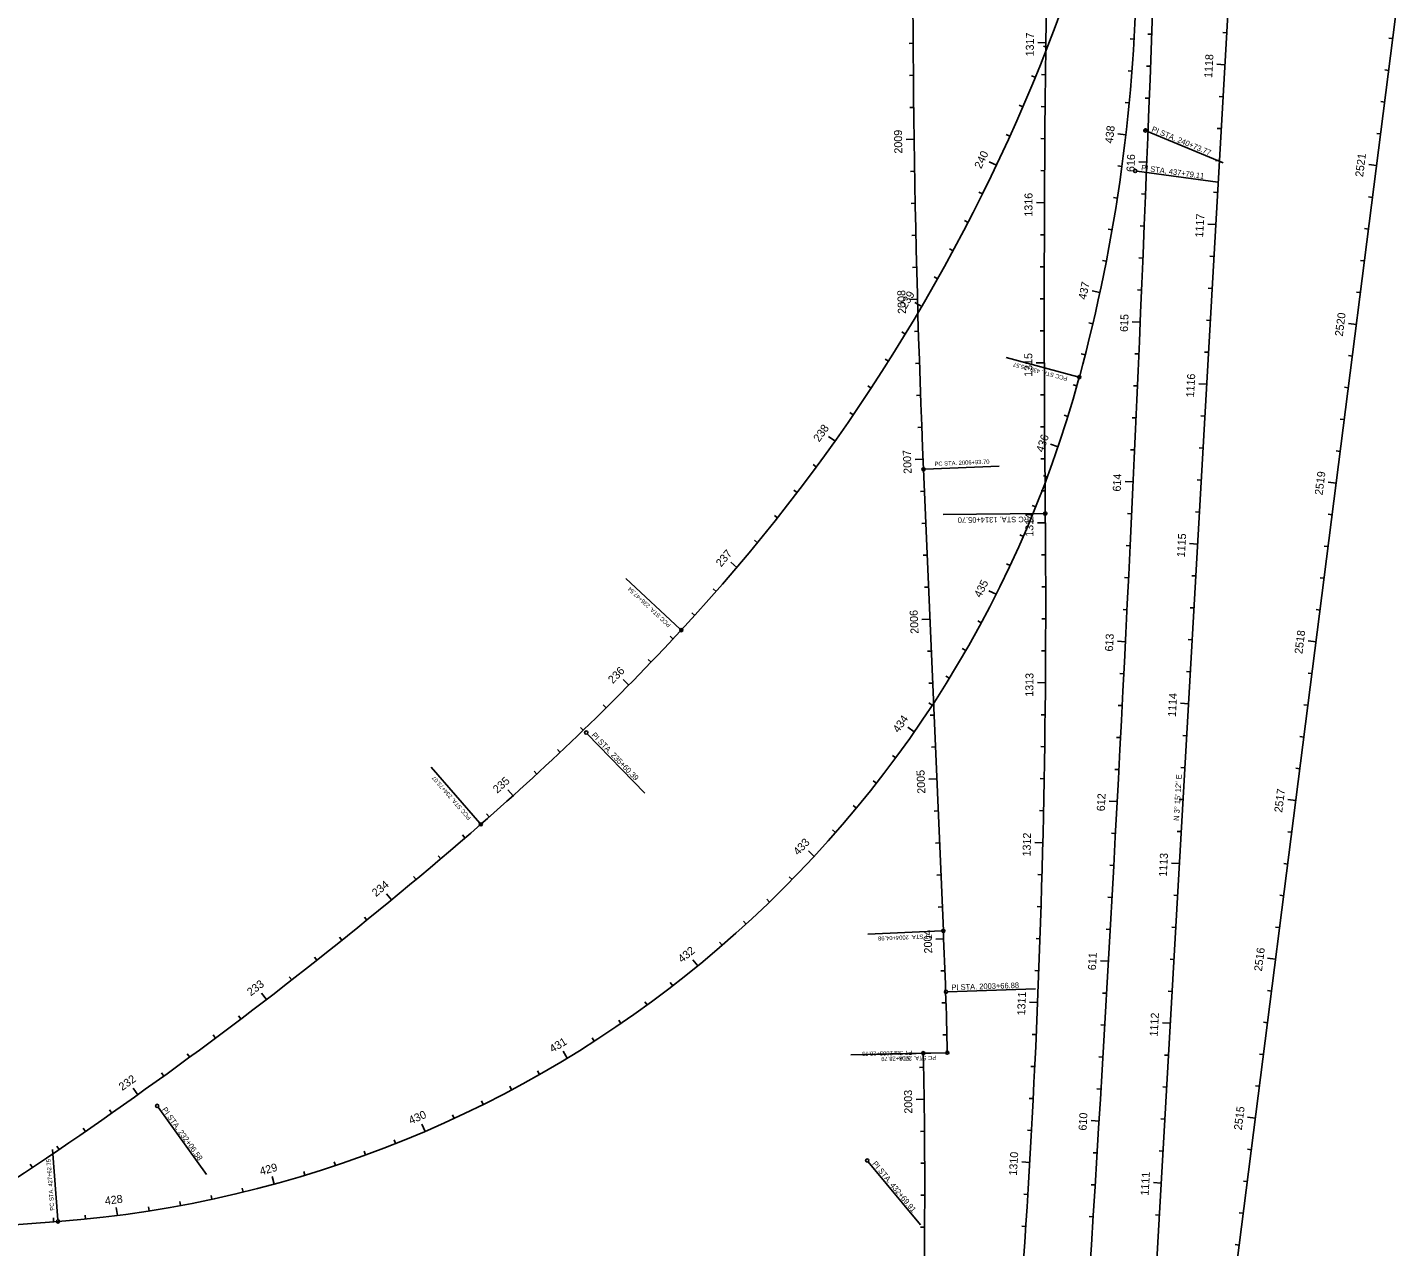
# Model space of a CAD drawing. Extents: x 919452 to 931278, y 583254 to 665650.
# Drawn here: x 928386 to 929242, y 636768 to 637530 of the extents above; entities that cross this region are included whole.
import ezdxf

# ---------------------------------------------------------------- set-up
doc = ezdxf.new("R2010")
doc.units = 0
for name, color, linetype in [('CLConst_dp', 7, 'Continuous'), ('CurveDataLabel_dp', 7, 'Continuous'), ('StationTicL_dp', 7, 'Continuous'), ('StationTicS_dp', 7, 'Continuous'), ('TextBLStation', 7, 'Continuous'), ('TextLabel', 7, 'Continuous')]:
    doc.layers.add(name, color=color, linetype=linetype)

msp = doc.modelspace()

# ---------------------------------------------------------------- linework, layer by layer
at = {"layer": 'CLConst_dp'}
for p, q in [((929063.91, 636273.75), (929152.38, 637830.35)), ((929141.47, 636757.31), (929241.91, 637546.46)), ((928958.02, 636965.18), (928945.65, 637253.64)), ((928945.5, 636888.7), (928960.5, 636889.03)), ((928197.18, 636767.96), (928404.75, 636783.58))]:
    msp.add_line(p, q, dxfattribs=at)
for centre, radius, start, end in [((900459.43, 638571.38), 28647.89, 355.955427, 0.622371), ((942221.08, 637355.55), 13200, 175.794488, 180.562502), ((936146.52, 637562.53), 7207.49, 175.47906, 182.456288), ((927949.43, 637937.64), 1152.92, 317.11857, 357.69675), ((928044.2, 637581.6), 1034.77, 344.85215, 359.56031), ((928350.92, 637498.56), 717, 274.3056, 344.85215), ((923022, 637167.05), 6000, 353.771004, 0.562502), ((927591.11, 638270.4), 1641.92, 311.0304, 317.11857), ((926819.39, 639157.21), 2817.49, 300.15904, 311.0304), ((925288.17, 636807.76), 3673.23, 1.26779, 2.45629), ((925288.17, 636807.76), 3658.23, 353.771, 1.26779)]:
    msp.add_arc(centre, radius, start, end, dxfattribs=at)
at = {"layer": 'CurveDataLabel_dp'}
for p, q in [((929085.21, 637465.04), (929132.92, 637445.19)), ((929078.9, 637439.97), (929129.62, 637433.03)), ((929042.04, 637311.46), (928997.3, 637323.57)), ((928946.65, 637253.68), (928992.91, 637255.67)), ((929020.71, 637225.95), (928957.88, 637225.33)), ((928793.51, 637153.78), (928759.54, 637185.33)), ((928735.53, 637088.4), (928771.53, 637051.21)), ((928668.31, 637032.55), (928637.88, 637067.52)), ((928957.02, 636965.14), (928910.78, 636963.16)), ((928960.65, 636927.15), (929015.58, 636928.94)), ((928944.5, 636888.68), (928900.21, 636887.7)), ((928959.5, 636889.01), (928913.2, 636887.98)), ((928944.5, 636888.68), (928925.34, 636888.25)), ((928467.3, 636854.99), (928497.46, 636812.86)), ((928404.68, 636784.58), (928401.37, 636828.45)), ((928911.12, 636820.89), (928943.74, 636781.43))]:
    msp.add_line(p, q, dxfattribs=at)
for centre in [(929084.29, 637465.42), (929077.91, 637440.11), (929043.01, 637311.2), (928945.65, 637253.64), (929021.71, 637225.96), (928794.25, 637153.1), (928734.83, 637089.12), (928668.96, 637031.8), (928958.02, 636965.18), (928959.65, 636927.12), (928945.5, 636888.7), (928945.5, 636888.7), (928960.5, 636889.03), (928466.72, 636855.8), (928910.48, 636821.66), (928404.75, 636783.58)]:
    msp.add_circle(centre, 1, dxfattribs=at)
at = {"layer": 'StationTicL_dp'}
for p, q in [((929022.1, 637520.25), (929017.1, 637520.31)), ((929133.97, 637506.45), (929128.98, 637506.74)), ((928939.76, 637459.85), (928934.76, 637459.78)), ((929072.11, 637462.72), (929067.14, 637463.3)), ((928991.2, 637443.74), (928986.68, 637445.88)), ((929085.19, 637445.59), (929080.19, 637445.78)), ((929228.8, 637443.42), (929223.84, 637444.05)), ((929021.24, 637420.26), (929016.24, 637420.28)), ((929128.3, 637406.62), (929123.31, 637406.9)), ((929055.84, 637364.09), (929050.96, 637365.15)), ((928941.88, 637359.87), (928936.88, 637359.73)), ((928944.5, 637355.35), (928940.18, 637357.87)), ((929081.08, 637345.67), (929076.09, 637345.88)), ((929216.17, 637344.22), (929211.21, 637344.85)), ((929021.12, 637320.26), (929016.12, 637320.24)), ((929122.62, 637306.78), (929117.63, 637307.06)), ((928890.31, 637271.34), (928886.23, 637274.23)), ((929029.71, 637267.63), (929024.98, 637269.24)), ((928945.38, 637259.93), (928940.39, 637259.72)), ((929076.63, 637245.77), (929071.64, 637246)), ((929203.55, 637245.02), (929198.59, 637245.65)), ((929021.77, 637220.26), (929016.77, 637220.21)), ((929116.95, 637206.94), (929111.96, 637207.22)), ((928829.06, 637192.34), (928825.24, 637195.57)), ((928991.02, 637175.5), (928986.55, 637177.76)), ((928949.66, 637160.02), (928944.67, 637159.81)), ((929071.83, 637145.89), (929066.83, 637146.13)), ((929190.92, 637145.82), (929185.96, 637146.45)), ((928761.4, 637118.73), (928757.83, 637122.24)), ((929021.82, 637120.26), (929016.82, 637120.3)), ((929111.27, 637107.1), (929106.28, 637107.38)), ((928939.89, 637089.66), (928935.78, 637092.51)), ((928953.95, 637060.12), (928948.95, 637059.9)), ((928689.13, 637049.64), (928685.78, 637053.36)), ((929066.68, 637046.02), (929061.69, 637046.28)), ((929178.29, 637046.62), (929173.33, 637047.25)), ((929020.21, 637020.27), (929015.21, 637020.4)), ((928877.33, 637011.75), (928873.66, 637015.14)), ((929105.6, 637007.26), (929100.61, 637007.54)), ((928613.22, 636984.55), (928610.04, 636988.4)), ((928958.23, 636960.21), (928953.24, 636960)), ((928804.54, 636943.3), (928801.38, 636947.17)), ((929061.18, 636946.17), (929056.19, 636946.45)), ((929165.67, 636947.42), (929160.71, 636948.06)), ((928535, 636922.26), (928531.95, 636926.23)), ((929016.93, 636920.33), (929011.93, 636920.53)), ((929099.92, 636907.42), (929094.93, 636907.71)), ((928722.94, 636885.63), (928720.35, 636889.9)), ((928454.61, 636862.79), (928451.71, 636866.86)), ((928946.02, 636859.92), (928941.03, 636859.85)), ((928634.12, 636839.86), (928632.15, 636844.45)), ((929055.33, 636846.34), (929050.34, 636846.64)), ((929153.04, 636848.22), (929148.08, 636848.86)), ((929011.98, 636820.45), (929006.99, 636820.74)), ((928539.8, 636806.89), (928538.48, 636811.71)), ((929094.25, 636807.58), (929089.26, 636807.87)), ((928441.81, 636787.35), (928441.18, 636792.3))]:
    msp.add_line(p, q, dxfattribs=at)
at = {"layer": 'StationTicS_dp'}
for p, q in [((929088.22, 637525.53), (929085.72, 637525.62)), ((929135.11, 637526.42), (929132.61, 637526.56)), ((928939.15, 637519.84), (928936.65, 637519.83)), ((929022.94, 637517.16), (929020.61, 637518.07)), ((929077.27, 637522.49), (929074.78, 637522.63)), ((929238.9, 637522.78), (929236.42, 637523.1)), ((929021.87, 637500.25), (929019.37, 637500.28)), ((929075.94, 637502.54), (929073.44, 637502.73)), ((929087.48, 637505.54), (929084.98, 637505.64)), ((929236.37, 637502.94), (929233.89, 637503.26)), ((928939.3, 637499.84), (928936.8, 637499.82)), ((929015.48, 637498.6), (929013.17, 637499.55)), ((929074.22, 637482.61), (929071.73, 637482.85)), ((929086.73, 637485.56), (929084.23, 637485.65)), ((929132.84, 637486.49), (929130.34, 637486.63)), ((929233.85, 637483.1), (929231.37, 637483.42)), ((928939.5, 637479.84), (928937, 637479.82)), ((929007.71, 637480.17), (929005.41, 637481.16)), ((929021.67, 637480.25), (929019.17, 637480.28)), ((929085.97, 637465.57), (929083.47, 637465.67)), ((929131.7, 637466.52), (929129.21, 637466.66)), ((928999.61, 637461.88), (928997.33, 637462.92)), ((929021.49, 637460.25), (929018.99, 637460.27)), ((929231.32, 637463.26), (929228.84, 637463.58)), ((929021.35, 637440.26), (929018.85, 637440.27)), ((929069.62, 637442.88), (929067.14, 637443.21)), ((929130.57, 637446.55), (929128.07, 637446.69)), ((928940.07, 637439.85), (928937.57, 637439.81)), ((928982.48, 637425.74), (928980.24, 637426.85)), ((929066.75, 637423.09), (929064.28, 637423.47)), ((929084.39, 637425.6), (929081.9, 637425.7)), ((929129.43, 637426.58), (929126.94, 637426.73)), ((929226.27, 637423.58), (929223.79, 637423.9)), ((928940.44, 637419.85), (928937.94, 637419.8)), ((928973.44, 637407.9), (928971.22, 637409.05)), ((929083.59, 637405.62), (929081.09, 637405.72)), ((928940.86, 637399.86), (928938.36, 637399.8)), ((929021.15, 637400.26), (929018.65, 637400.26)), ((929063.49, 637403.35), (929061.03, 637403.78)), ((929223.75, 637403.74), (929221.27, 637404.06)), ((928964.1, 637390.22), (928961.9, 637391.4)), ((929021.1, 637380.26), (929018.6, 637380.26)), ((929059.86, 637383.69), (929057.41, 637384.16)), ((929082.77, 637385.64), (929080.27, 637385.74)), ((929127.16, 637386.65), (929124.67, 637386.79)), ((929221.22, 637383.9), (929218.74, 637384.22)), ((928941.34, 637379.86), (928938.84, 637379.8)), ((928954.45, 637372.7), (928952.27, 637373.92)), ((929081.93, 637365.65), (929079.43, 637365.76)), ((929126.03, 637366.68), (929123.53, 637366.82)), ((929218.7, 637364.06), (929216.22, 637364.38)), ((929021.08, 637360.26), (929018.58, 637360.26)), ((929124.89, 637346.71), (929122.4, 637346.85)), ((928934.25, 637338.18), (928932.11, 637339.48)), ((928942.47, 637339.88), (928939.97, 637339.8)), ((929021.09, 637340.26), (929018.59, 637340.25)), ((929051.45, 637344.58), (929049.02, 637345.16)), ((928923.7, 637321.18), (928921.59, 637322.52)), ((929046.68, 637325.16), (929044.26, 637325.78)), ((929080.22, 637325.69), (929077.72, 637325.8)), ((929123.76, 637326.74), (929121.26, 637326.89)), ((929213.65, 637324.38), (929211.17, 637324.7)), ((928943.11, 637319.89), (928940.61, 637319.8)), ((928912.86, 637304.38), (928910.77, 637305.75)), ((929041.53, 637305.83), (929039.13, 637306.51)), ((929079.34, 637305.71), (929076.85, 637305.82)), ((929211.12, 637304.54), (929208.64, 637304.86)), ((928943.81, 637299.9), (928941.31, 637299.81)), ((929021.19, 637300.26), (929018.69, 637300.25)), ((928901.73, 637287.76), (928899.67, 637289.17)), ((929035.89, 637286.65), (929033.5, 637287.39)), ((929078.45, 637285.73), (929075.96, 637285.84)), ((929121.49, 637286.81), (929118.99, 637286.95)), ((928944.57, 637279.92), (928942.07, 637279.82)), ((929021.29, 637280.26), (929018.79, 637280.24)), ((929208.6, 637284.7), (929206.12, 637285.02)), ((929021.42, 637260.26), (929018.92, 637260.24)), ((929077.55, 637265.75), (929075.05, 637265.86)), ((929120.35, 637266.84), (929117.86, 637266.98)), ((929206.07, 637264.86), (929203.59, 637265.18)), ((928878.62, 637255.12), (928876.6, 637256.6)), ((929023.01, 637248.78), (929020.66, 637249.66)), ((929119.22, 637246.87), (929116.72, 637247.02)), ((928866.64, 637239.1), (928864.65, 637240.62)), ((928946.24, 637239.95), (928943.74, 637239.84)), ((929021.58, 637240.26), (929019.08, 637240.24)), ((929015.78, 637230.14), (929013.46, 637231.07)), ((929075.7, 637225.79), (929073.2, 637225.91)), ((929118.08, 637226.91), (929115.59, 637227.05)), ((928854.38, 637223.3), (928852.42, 637224.85)), ((928947.09, 637219.97), (928944.59, 637219.86)), ((929201.02, 637225.18), (929198.54, 637225.5)), ((928841.85, 637207.71), (928839.92, 637209.29)), ((929008.04, 637211.7), (929005.74, 637212.7)), ((929021.91, 637200.26), (929019.41, 637200.24)), ((929074.75, 637205.81), (929072.25, 637205.93)), ((929198.5, 637205.34), (929196.02, 637205.66)), ((928947.95, 637199.99), (928945.45, 637199.88)), ((928999.78, 637193.48), (928997.52, 637194.55)), ((929073.79, 637185.84), (929071.29, 637185.96)), ((929115.81, 637186.97), (929113.32, 637187.11)), ((929195.97, 637185.5), (929193.49, 637185.82)), ((928816, 637177.19), (928814.12, 637178.84)), ((928948.81, 637180.01), (928946.31, 637179.9)), ((929021.99, 637180.26), (929019.49, 637180.25)), ((929072.82, 637165.86), (929070.32, 637165.98)), ((929114.68, 637167), (929112.18, 637167.14)), ((929193.45, 637165.66), (929190.97, 637165.98)), ((928802.68, 637162.27), (928800.83, 637163.95)), ((928981.76, 637157.78), (928979.56, 637158.97)), ((929022, 637160.26), (929019.5, 637160.26)), ((928789.1, 637147.58), (928787.28, 637149.29)), ((928972.01, 637140.32), (928969.84, 637141.57)), ((929021.94, 637140.26), (929019.44, 637140.27)), ((929113.54, 637147.03), (929111.05, 637147.18)), ((928775.34, 637133.07), (928773.53, 637134.81)), ((928950.52, 637140.04), (928948.02, 637139.93)), ((928961.78, 637123.13), (928959.65, 637124.44)), ((929070.83, 637125.91), (929068.33, 637126.04)), ((929112.41, 637127.07), (929109.91, 637127.21)), ((929188.4, 637125.98), (929185.92, 637126.3)), ((928951.38, 637120.06), (928948.88, 637119.95)), ((928747.28, 637104.56), (928745.52, 637106.34)), ((928951.07, 637106.24), (928948.97, 637107.61)), ((929069.81, 637105.94), (929067.31, 637106.06)), ((929185.87, 637106.14), (929183.39, 637106.46)), ((928952.24, 637100.08), (928949.74, 637099.97)), ((929021.63, 637100.26), (929019.13, 637100.29)), ((928733, 637090.57), (928731.26, 637092.36)), ((929068.78, 637085.96), (929066.28, 637086.09)), ((929110.14, 637087.13), (929107.64, 637087.27)), ((929183.34, 637086.3), (929180.86, 637086.62)), ((928718.54, 637076.75), (928716.82, 637078.56)), ((928928.26, 637073.39), (928926.24, 637074.87)), ((928953.09, 637080.1), (928950.59, 637079.99)), ((929021.37, 637080.26), (929018.87, 637080.3)), ((928703.92, 637063.1), (928702.22, 637064.94)), ((929067.74, 637065.99), (929065.24, 637066.12)), ((929109, 637067.16), (929106.51, 637067.31)), ((929180.82, 637066.46), (929178.34, 637066.78)), ((928916.18, 637057.45), (928914.2, 637058.99)), ((929021.05, 637060.26), (929018.55, 637060.31)), ((929107.87, 637047.2), (929105.37, 637047.34)), ((928674.18, 637036.35), (928672.53, 637038.23)), ((928903.65, 637041.86), (928901.73, 637043.45)), ((928954.81, 637040.13), (928952.31, 637040.03)), ((929020.66, 637040.27), (929018.16, 637040.32)), ((928659.08, 637023.24), (928657.45, 637025.13)), ((928890.7, 637026.62), (928888.82, 637028.27)), ((929065.61, 637026.05), (929063.11, 637026.18)), ((929106.73, 637027.23), (929104.24, 637027.37)), ((929175.77, 637026.78), (929173.29, 637027.1)), ((928643.89, 637010.23), (928642.27, 637012.14)), ((928955.66, 637020.15), (928953.17, 637020.05)), ((929064.52, 637006.08), (929062.02, 637006.21)), ((929173.24, 637006.94), (929170.76, 637007.26)), ((928628.6, 636997.33), (928626.99, 636999.25)), ((928863.55, 636997.26), (928861.76, 636999)), ((928956.52, 637000.17), (928954.02, 637000.06)), ((929019.68, 637000.28), (929017.18, 637000.35)), ((929063.42, 636986.11), (929060.92, 636986.24)), ((929104.46, 636987.29), (929101.97, 636987.43)), ((929170.72, 636987.1), (929168.24, 636987.42)), ((928849.36, 636983.15), (928847.63, 636984.95)), ((928957.38, 636980.19), (928954.88, 636980.08)), ((929019.09, 636980.29), (929016.6, 636980.37)), ((928597.75, 636971.87), (928596.18, 636973.81)), ((928834.8, 636969.45), (928833.11, 636971.3)), ((928582.2, 636959.3), (928580.63, 636961.25)), ((929062.31, 636966.14), (929059.81, 636966.28)), ((929103.33, 636967.32), (929100.83, 636967.47)), ((929168.19, 636967.26), (929165.71, 636967.58)), ((928819.85, 636956.16), (928818.22, 636958.06)), ((929018.44, 636960.3), (929015.94, 636960.39)), ((928566.55, 636946.84), (928565, 636948.8)), ((929102.19, 636947.36), (929099.7, 636947.5)), ((928550.82, 636934.49), (928549.28, 636936.47)), ((928959.01, 636940.22), (928956.51, 636940.13)), ((929017.72, 636940.31), (929015.22, 636940.41)), ((928788.88, 636930.86), (928787.35, 636932.84)), ((929060.04, 636926.2), (929057.54, 636926.35)), ((929101.06, 636927.39), (929098.56, 636927.53)), ((929163.14, 636927.58), (929160.66, 636927.9)), ((928772.87, 636918.87), (928771.4, 636920.89)), ((928959.67, 636920.23), (928957.18, 636920.16)), ((928519.09, 636910.14), (928517.58, 636912.13)), ((928756.54, 636907.32), (928755.13, 636909.39)), ((929058.88, 636906.24), (929056.39, 636906.38)), ((929160.62, 636907.74), (929158.14, 636908.06)), ((928503.09, 636898.13), (928501.6, 636900.13)), ((928739.89, 636896.24), (928738.54, 636898.34)), ((928960.23, 636900.24), (928957.73, 636900.18)), ((929016.07, 636900.35), (929013.57, 636900.46)), ((928487.02, 636886.24), (928485.54, 636888.25)), ((929057.71, 636886.27), (929055.22, 636886.42)), ((929098.79, 636887.45), (929096.29, 636887.6)), ((929158.09, 636887.9), (929155.61, 636888.22)), ((928470.85, 636874.46), (928469.39, 636876.48)), ((928705.7, 636875.49), (928704.47, 636877.66)), ((928945.69, 636879.91), (928943.19, 636879.87)), ((929015.15, 636880.37), (929012.65, 636880.49)), ((928688.19, 636865.84), (928687.01, 636868.04)), ((929056.53, 636866.3), (929054.03, 636866.45)), ((929097.65, 636867.49), (929095.16, 636867.63)), ((929155.57, 636868.06), (929153.09, 636868.38)), ((928670.41, 636856.68), (928669.3, 636858.91)), ((929014.16, 636860.39), (929011.66, 636860.52)), ((928438.28, 636851.24), (928436.84, 636853.29)), ((928652.38, 636848.02), (928651.33, 636850.28)), ((928421.87, 636839.81), (928420.45, 636841.86)), ((929013.1, 636840.42), (929010.61, 636840.56)), ((929096.52, 636847.52), (929094.02, 636847.66)), ((928615.64, 636832.22), (928614.72, 636834.54)), ((928946.26, 636839.92), (928943.76, 636839.9)), ((928405.38, 636828.49), (928403.97, 636830.56)), ((928596.95, 636825.09), (928596.09, 636827.44)), ((929054.12, 636826.38), (929051.63, 636826.53)), ((929095.38, 636827.55), (929092.89, 636827.69)), ((929150.52, 636828.38), (929148.04, 636828.7)), ((928388.81, 636817.29), (928387.42, 636819.37)), ((928578.07, 636818.49), (928577.28, 636820.87)), ((928946.38, 636819.92), (928943.88, 636819.91)), ((928559.02, 636812.42), (928558.29, 636814.82)), ((929052.9, 636806.41), (929050.4, 636806.57)), ((929147.99, 636808.54), (929145.51, 636808.86)), ((928500.94, 636797.43), (928500.42, 636799.88)), ((928520.44, 636801.89), (928519.84, 636804.32)), ((928946.39, 636799.92), (928943.89, 636799.92)), ((929010.79, 636800.49), (929008.3, 636800.64)), ((928461.61, 636790.16), (928461.23, 636792.63)), ((928481.33, 636793.52), (928480.87, 636795.98)), ((928402.01, 636783.38), (928401.83, 636785.87)), ((928421.94, 636785.09), (928421.69, 636787.57)), ((929009.54, 636780.53), (929007.04, 636780.69)), ((929051.66, 636786.45), (929049.16, 636786.61)), ((929093.11, 636787.61), (929090.62, 636787.76)), ((929145.47, 636788.7), (929142.99, 636789.02)), ((928946.29, 636779.92), (928943.79, 636779.94)), ((929142.94, 636768.86), (929140.46, 636769.18))]:
    msp.add_line(p, q, dxfattribs=at)

# ---------------------------------------------------------------- texts
at = {"layer": 'CurveDataLabel_dp'}
for s, height, rotation, p in [('PI STA. 240+73.77', 3.5, 337.40766, (929087.86, 637464.88)), ('PI STA. 437+79.11', 3.5, 352.20623, (929081.49, 637440.5)), ('PCC STA. 436+45.57', 2.625, 164.85215, (929035.79, 637311.34)), ('PC STA. 2006+93.70', 2.625, 2.45629, (928952.57, 637255.69)), ('PRC STA. 1314+05.70', 3.5, 180.5625, (929014.73, 637224.14)), ('PCC STA. 236+47.54', 2.625, 137.11857, (928787.93, 637156.58)), ('PI STA. 235+60.39', 3.5, 314.07448, (928737.89, 637087.21)), ('PCC STA. 234+73.07', 2.625, 131.0304, (928663.05, 637035.93)), ('PT STA. 2004+04.98', 2.625, 182.45629, (928951.1, 636963.14)), ('PI STA. 2003+66.88', 3.5, 1.86204, (928963.12, 636928.11)), ('PT Sta 2003+28.79', 2.625, 181.26779, (928938.46, 636890.29)), ('PC STA. 2003+28.79', 2.625, 181.26779, (928953.54, 636887.13)), (' STA. ', 2.625, 181.26779, (928938.54, 636886.79)), ('PI STA. 232+06.58', 3.5, 305.59472, (928469.47, 636853.46)), ('PC STA. 427+62.75', 2.625, 94.3056, (928402.48, 636790.43)), ('PI STA. 432+69.91', 3.5, 309.57888, (928913.39, 636819.52))]:
    msp.add_text(s, height=height, rotation=rotation, dxfattribs=at).set_placement(p)
at = {"layer": 'TextBLStation'}
for s, rotation, p in [('1317', 89.28507, (929014.5, 637511.63)), ('1118', 86.74679, (929125.99, 637498.08)), ('438', 83.40331, (929063.91, 637457.06)), ('2009', 90.81632, (928932.38, 637450.96)), ('240', 64.63446, (928981.63, 637441.06)), ('616', 87.74782, (929077.44, 637439.35)), ('2521', 82.74679, (929220.3, 637436.06)), ('1316', 89.71913, (929013.69, 637411.51)), ('1117', 86.74679, (929120.32, 637398.34)), ('2008', 91.61127, (928934.63, 637350.85)), ('239', 59.66482, (928934.73, 637353.5)), ('437', 77.86623, (929047.15, 637359.34)), ('615', 87.54782, (929073.31, 637339.43)), ('2520', 82.74679, (929207.62, 637336.47)), ('1315', 90.15319, (929013.65, 637311.43)), ('1116', 86.74679, (929114.64, 637298.44)), ('238', 54.69517, (928880.4, 637270.31)), ('436', 71.21099, (929020.51, 637263.86)), ('2007', 92.40622, (928938.25, 637250.91)), ('2519', 82.74679, (929195, 637237.26)), ('614', 87.34782, (929068.84, 637239.64)), ('1314', 90.50807, (929014.34, 637211.46)), ('1115', 86.74679, (929108.96, 637198.57)), ('237', 49.72553, (928819.15, 637192.25)), ('435', 63.21995, (928981.36, 637173.02)), ('2006', 92.45629, (928942.55, 637150.93)), ('613', 87.14782, (929064.01, 637139.68)), ('2518', 82.74679, (929182.37, 637138.02)), ('236', 45.45955, (928751.47, 637119.34)), ('1313', 89.55314, (929014.25, 637111.48)), ('1114', 86.74679, (929103.29, 637098.81)), ('434', 55.2289, (928930.03, 637088.6)), ('2005', 92.45629, (928946.83, 637050.99)), ('235', 41.96999, (928679.23, 637050.82)), ('612', 86.94782, (929058.84, 637039.84)), ('2517', 82.74679, (929169.75, 637038.92)), ('433', 47.23786, (928867.35, 637012)), ('1312', 88.59821, (929012.49, 637011.63)), ('1113', 86.74679, (929097.61, 636998.87)), ('234', 39.54438, (928603.44, 636986.2)), ('2004', 92.3786, (928951.1, 636951.17)), ('432', 39.24682, (928794.69, 636944.94)), ('2516', 82.74679, (929157.12, 636939.66)), ('611', 86.74782, (929053.34, 636940.47)), ('233', 37.51081, (928525.2, 636924.2)), ('1311', 87.64328, (929009.09, 636912.26)), ('1112', 86.74679, (929091.94, 636899.03)), ('431', 31.25577, (928713.81, 636888.85)), ('232', 35.47724, (928444.89, 636865.08)), ('2003', 90.81694, (928938.65, 636850.98)), ('430', 23.26473, (928625.17, 636844.17)), ('610', 86.54782, (929047.45, 636840.28)), ('2515', 82.74679, (929144.49, 636840.43)), ('1310', 86.68835, (929003.99, 636812.13)), ('429', 15.27369, (928531.52, 636812.4)), ('1111', 86.74679, (929086.29, 636799.64)), ('428', 7.28264, (928434.34, 636793.95))]:
    msp.add_text(s, height=5, rotation=rotation, dxfattribs=at).set_placement(p)
at = {"layer": 'TextLabel'}
msp.add_text('N 3%%d 15\' 12" E', height=3.5, rotation=86.74679, dxfattribs=at).set_placement((929105.36, 637033.86))

doc.saveas('drawing.dxf')
